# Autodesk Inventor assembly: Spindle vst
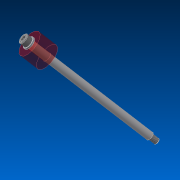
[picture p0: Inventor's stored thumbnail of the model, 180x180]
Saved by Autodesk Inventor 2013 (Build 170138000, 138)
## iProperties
Shininess: 20.0
Length Units: 11269
Angle Units: 11279
Time Units: 11290
Mass Units: 11283
Length Display Precision: 3
Angle Display Precision: 2
Created: 2001-04
Part Number: Spindle vst
Document SubType Name: Baugruppe
Designer: dl
Density: 0.0
Volumn: 0.0
Area: 0.0
PropertySet Name: Model Information
Control State: 0
Master: False
Checked Out: False
Author: dl
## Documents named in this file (5)
- C:\Webworld\Webworld2014\ATC2013\Assemblies\ATC-Baby Carriage\DAMPER\Spindle vst.iam
- C:\Webworld\Webworld2014\ATC2013\Assemblies\ATC-Baby Carriage\DAMPER\Spindle.ipt
- C:\Webworld\Webworld2014\ATC2013\Assemblies\ATC-Baby Carriage\DAMPER\DIN 912 - M6 x 10.ipt
- C:\Webworld\Webworld2014\ATC2013\Assemblies\ATC-Baby Carriage\DAMPER\U-disc.ipt
- C:\Webworld\Webworld2014\ATC2013\Assemblies\ATC-Baby Carriage\DAMPER\Damper_element_big_spindle.ipt
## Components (4 placed, 4 different names)
1. Spindle:1 — Insert:1
2. U-disc:1 — Insert:1, Insert:2, Insert:3
3. Damper_element_big_spindle:1 — Insert:2
4. DIN 912 - M6 x 10:1 — Insert:3
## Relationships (3: Insert 3)
- Insert:1: Spindle:1 ↔ U-disc:1
- Insert:2: U-disc:1 ↔ Damper_element_big_spindle:1
- Insert:3: U-disc:1 ↔ DIN 912 - M6 x 10:1
